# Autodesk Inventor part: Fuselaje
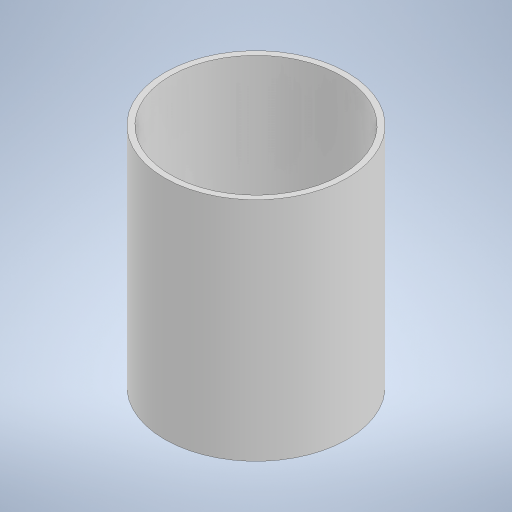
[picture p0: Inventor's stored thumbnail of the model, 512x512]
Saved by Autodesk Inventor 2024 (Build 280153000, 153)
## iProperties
Created: 2024-05
Part Number: Fuselaje
Material: Generic
Document SubType Name: Modeling
Designer: dylan
Density: 1 g/cm^3
Appearance: Default
Author: dylan
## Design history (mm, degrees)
sketch "Sketch1"
  geometry: C1 r 75.65 at (0, 0); C2 r 80.65 at (0, 0); 1 further point
  constraints: 2 centre point, 2 coincident
  dimensions: "d0" = 151.3 diameter of C1; "d1" = 161.3 diameter of C2
extrude "Extrusion1" new body sketch "Sketch1" distance "d2" = 200; taper "d3" = 0 deg
body "Solid1"
